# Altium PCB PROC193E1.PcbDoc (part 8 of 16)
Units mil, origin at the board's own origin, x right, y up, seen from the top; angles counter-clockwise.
Board outline 7700 x 2300 mil, 6 copper layers (Top Layer, GND 1, SIG 1, PWR, GND 2, Bottom Layer), stack 60.98 mil thick; 946 components, 667 nets, 9401 pads, 1730 vias.
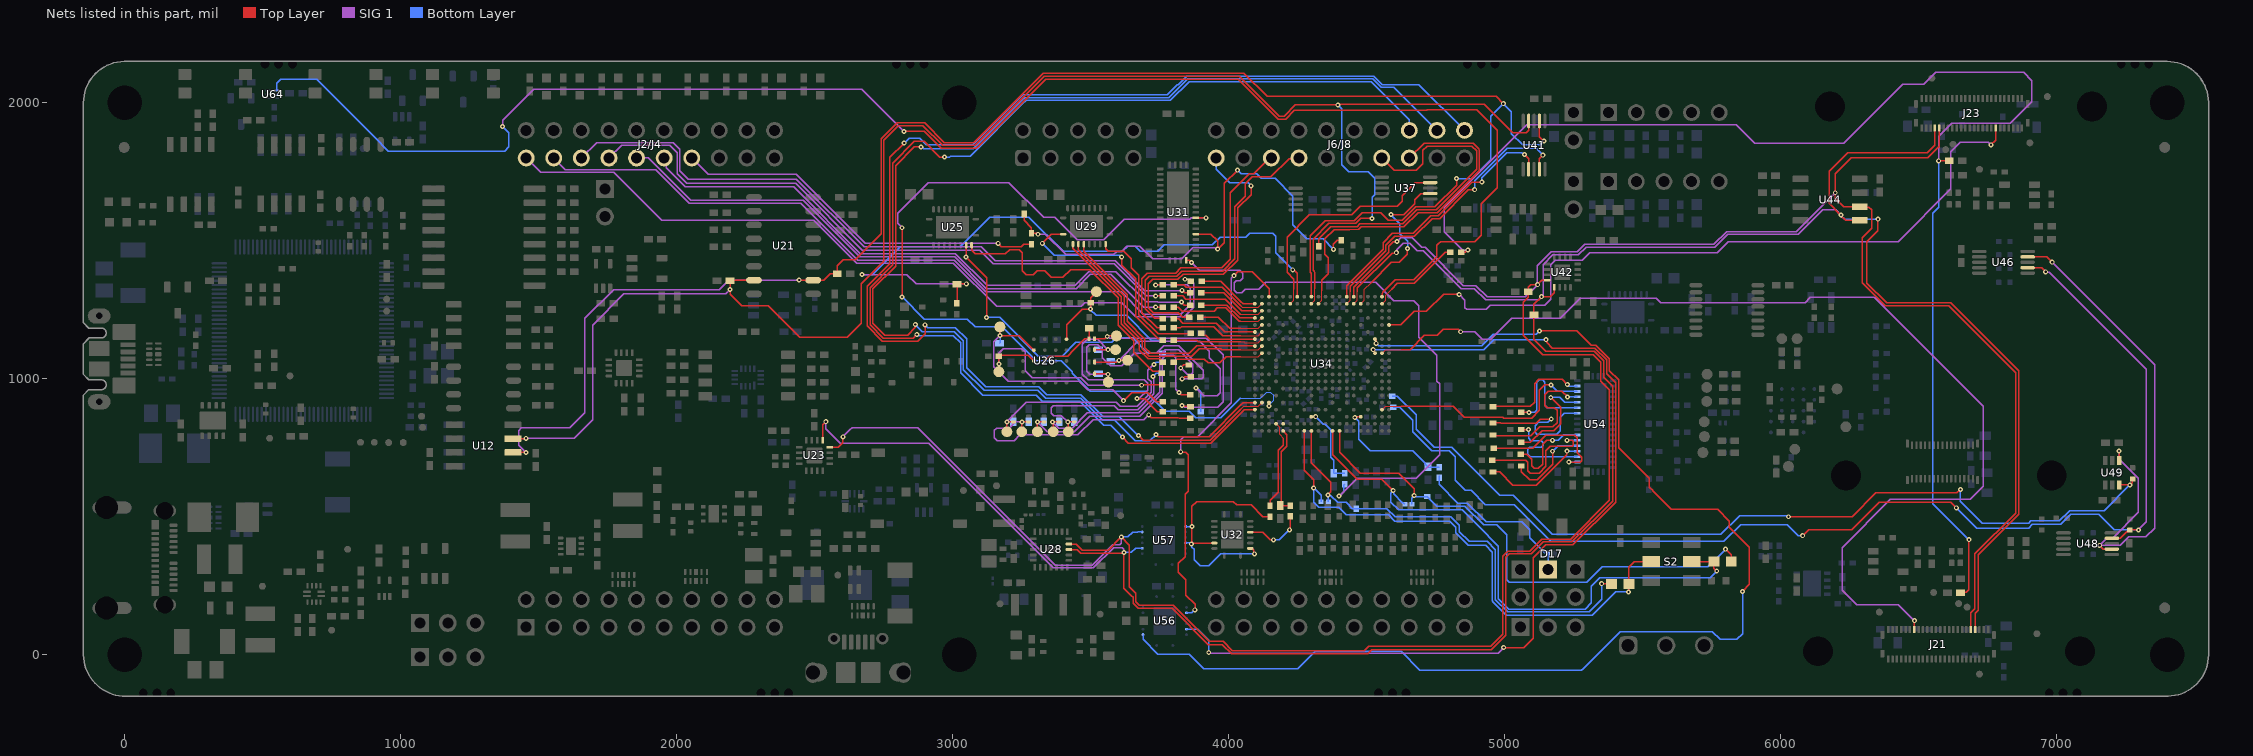
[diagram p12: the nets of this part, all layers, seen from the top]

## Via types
v1: diameter 18, hole 8, Top Layer to Bottom Layer, tented both sides, 1710 vias
v2: diameter 18, hole 8, Top Layer to Bottom Layer, tented top, 12 vias
v3: diameter 23.62, hole 11.81, Top Layer to Bottom Layer, tented both sides, 8 vias

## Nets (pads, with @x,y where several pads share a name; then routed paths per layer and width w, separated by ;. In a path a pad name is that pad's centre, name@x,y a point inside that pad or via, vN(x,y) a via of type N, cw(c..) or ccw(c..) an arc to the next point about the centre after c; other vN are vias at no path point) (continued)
AM261_ADC2_AIN5: R315.1 U31.21 | length 2081.7
  Top Layer w5.3: U31.21@3845.61,1429.75 3856.89,1429.75 v1(3865.32,1421.32)
  SIG 1 w4.75: v1(3865.32,1421.32) 3893.79,1392.84 4039.91,1392.84 4051,1381.76 4051,1365 4041.56,1355.56 4027.59,1355.56 4019.89,1347.85 4019.89,1320.44 4028.61,1311.72 4047.69,1311.72 4059.57,1323.6 4108.47,1323.6 4134.1,1349.23 4531.57,1349.23 4597.21,1283.59 4670.54,1283.59 4689.13,1265 4689.13,1150.02 4754.17,1084.98 4754.17,991.71 4764.6,981.28 4764.6,725.6 4678.9,639.9 4464.59,639.9 v1(4399.51,574.83)
  Bottom Layer w5.3: v1(4399.51,574.83) 4400.94,574.83 4416.39,590.27 4416.39,615.07 R315.1@4419.55,618.24
AM261_ADC2_AIN5_R: C195.2 R315.2 U34.V9 | length 291.8
  Top Layer w5.3: U34.V9@4299.21,862.57 4314.56,862.56 v1(4314.84,862.84)
  Bottom Layer w5.3: v1(4314.84,862.84) 4342.43,835.25 4350.06,835.25 4369.2,816.11 4369.2,767.84 4369.2,715.18 4379.69,704.7 C195.2@4379.69,658.31 4380.39,657.61 R315.2@4419.55,657.61
AM261_ADC2_AIN6: R136.1 U32.13 | length 218.4
  Top Layer w5.3: U32.13@4077.76,444.34 4123.6,444.34 4150.19,417.74 4161.25,417.74 v1(4162.41,416.58) ; v1(4219.9,452.91) 4219.9,456.34 4223.28,459.72 R136.1@4223.28,501.25
  Bottom Layer w5.3: v1(4162.41,416.58) 4183.58,416.58 v1(4219.9,452.91)
AM261_ADC2_AIN6_R: C90.2 R136.2 U34.Y5 | length 315.2
  Top Layer w5.3: C90.2@4186.24,540.73 4223.17,540.73 R136.2@4223.28,540.62 ; C90.2@4189.85,547.12 4189.85,735.85 4210.1,756.1 4210.1,798.13 U34.Y5@4196.85,811.38
AM261_ADC_CAL0: D17.1 J14.1 R307.1 | length 603.3
  Bottom Layer w5.3: R307.1@4762.73,649.07 4762.73,617.18 4830.22,549.68 4864.46,549.68 4932.96,481.18 5060.82,481.18 5089.67,452.33 5089.67,423.67 5143.89,369.44 5153.12,369.44 D17.1@5156.57,365.99 J14.1@5156.57,309.25
AM261_ADC_CAL0_R: C164.2 R307.2 U34.V16 | length 442.1
  Top Layer w5.3: v1(4456.52,860.06) 4459.02,862.57 U34.V16@4478.34,862.57
  Bottom Layer w5.3: v1(4456.52,860.06) 4471.02,845.56 4471.02,780.8 4511.7,740.12 4666.93,740.12 4712.57,694.48 4712.57,690.39 C164.2@4721.73,681.23 ; C164.2@4723.13,680.02 R307.2@4762.73,680.02
AM261_ADC_VREFHI_G0: C113.1 C166.1 S2.2 U34.Y12 | length 2138.3
  Top Layer w5.3: U34.Y12@4375.98,811.38 4375.98,725.09 4464.57,636.5 4553.95,636.5 v1(4595.63,594.82) ; S2.2@5676.66,337.83 5757.22,337.83 C113.1@5757.57,338.19 5757.57,313.53 v1(5767.94,303.16)
  Bottom Layer w5.3: C166.1@4637.72,545.95 4632.1,551.56 4628.84,551.56 4597.29,583.12 4597.29,593.16 v1(4595.63,594.82) 4595.63,593.45 4587.55,585.37 4587.55,552.42 4614.86,525.11 4845.97,525.11 4903,468.08 4977,394.09 4977,203.82 5014.88,165.93 5290.93,165.93 5313.32,188.32 5313.32,248.55 5344.22,279.45 5744.23,279.45 v1(5767.94,303.16)
AM261_ADC_VREFHI_G1: C111.1 C199.1 S2.5 U34.Y8 | length 1977.4
  Top Layer w5.3: U34.Y8@4273.62,811.38 4273.62,669.12 4308.05,634.69 4308.05,605.17 v1(4307.44,604.57) ; v1(5448.47,228.03) 5448.47,255.91 C111.1@5449.34,256.77 5449.34,317.67 5469.51,337.83 S2.5@5530.99,337.83
  Bottom Layer w5.3: C199.1@4334.68,554.56 4334.68,577.33 v1(4307.44,604.57) 4307.44,553.23 4325.2,535.48 4397.52,535.48 4425.88,507.12 4564.11,507.12 4564.41,506.82 4579.22,506.82 4601.92,484.13 4800.79,484.13 4822.14,462.78 4822.14,441.65 4867.72,396.06 4930.94,396.06 4955.4,371.6 4955.4,195.44 4956,194.84 4956,192.56 5005.75,142.8 5019.53,142.8 5019.73,143 5274.39,143 5274.59,142.8 5317.6,142.8 5402.82,228.03 v1(5448.47,228.03)
AM261_ADC_VREFLO_G0: C113.2 C166.2 R308.2 U34.Y13 | length 1918
  Top Layer w5.3: U34.Y13@4401.57,811.38 4401.57,733.27 4477.14,657.7 4615.46,657.7 4671.66,601.5 v1(4671.66,576.85) ; v1(5799.88,382.57) 5820.57,361.89 C113.2@5820.57,338.19
  Bottom Layer w5.3: C166.2@4663.7,545.95 4663.7,567.4 4671.66,575.36 v1(4671.66,576.85) 4674.25,576.85 4677.62,573.48 R308.2@4718.66,573.48 4753.62,538.53 4855.46,538.53 4923.63,470.36 4971.17,470.36 5006.69,434.85 5006.69,272.77 5016.78,262.68 5034.19,262.68 5034.37,262.86 5078.78,262.86 5078.96,262.68 5134.19,262.68 5134.37,262.86 5178.78,262.86 5178.96,262.68 5234.19,262.68 5234.37,262.86 5278.78,262.86 5278.96,262.68 5297.46,262.68 5352.94,318.15 5735.47,318.15 v1(5799.88,382.57)
AM261_ADC_VREFLO_G1: C111.2 C199.2 R314.2 U34.Y9 | length 1688.6
  Top Layer w5.3: U34.Y9@4299.21,811.38 4299.21,767.84 4299.21,695.3 4368.81,625.7 4368.81,589.87 4359.67,580.73 v1(4359.67,579.37) ; v1(5350.99,257.78) 5352.18,256.59 5386.16,256.59 C111.2@5386.35,256.77
  Bottom Layer w5.3: C199.2@4360.67,554.56 4360.67,578.37 v1(4359.67,579.37) 4362.1,576.94 4369.8,576.94 4394.49,552.24 4394.49,552.18 4424.86,552.18 4447.13,529.91 R314.2@4461.48,529.91 4573.07,529.91 4602.27,500.71 4803.97,500.71 4835.37,469.31 4835.37,445.73 4870.37,410.73 4936.27,410.73 4966,381 4966,199.83 5010.49,155.33 5295.32,155.33 5295.62,155.63 5305.92,155.63 5350.99,200.7 v1(5350.99,257.78)
AM261_ATESTV1: U34.W5
AM261_CLKOUT1: R157.1 R212.1 R213.1 | length 4873
  Top Layer w5.3: R157.1@4842.51,1457.97 4857.34,1457.97 v1@4865.9,1466.52 ; v1(6572.19,1789.93) 6572.34,1790.07 R213.1@6610.58,1790.07 ; R212.1@6651.32,224.48 6652.68,225.85 6671.91,225.85 6681.59,235.53 v1(6681.59,416.99)
  SIG 1 w4.75: v1(4865.97,1466.59) 4847.42,1466.59 4781.16,1532.85 4781.16,1621.74 5079.45,1920.03 5838.97,1920.03 5905.97,1853.03 6228.18,1853.03 6442.43,2067.28 6518.67,2067.28 6561.91,2110.52 6879.72,2110.52 6909.45,2080.79 6909.45,2002.93 6831.71,1925.19 6618.56,1925.19 6572.19,1878.83 v1(6572.19,1789.93)
  Bottom Layer w5.3: v1(6572.19,1789.93) 6572.19,1621.22 6550.49,1599.52 6550.49,548.09 v1(6681.59,416.99)
AM261_CLKOUT1_R: R157.2 U34.B19 | length 332.6
  Top Layer w3.94: U34.B19@4555.12,1272.01 4567.87,1284.77 4567.87,1292.27 4567.91,1292.3 4567.91,1302.9 4590.17,1325.16
  Top Layer w5.3: 4590.17,1325.16 4611.01,1346 4672.07,1346 4784.04,1457.97 R157.2@4800.14,1457.97
AM261_DAC_OUT: R134.1 U32.6 U32.10 U57.2 U57.5 | length 912.9
  Top Layer w5.3: v1(3864.16,401.48) 3867.6,401.48 3871.08,404.97 U32.6@3947.84,404.97 ; v1@3865.68,403 3865.68,464.02 v1(3866.46,464.8) 3866.46,537.98 3883.59,555.11 4016.71,555.11 4028.33,543.49 4080.99,543.49 4123.75,500.73 R134.1@4149.38,500.73 ; U32.10@4077.76,385.28 4083.73,385.28 4090.85,378.15 4090.85,368.31 v1(4093.28,365.88)
  Bottom Layer w5.3: U57.5@3843.79,405.78 3844.42,405.15 v1@3864.16,405.15 ; U57.2@3843.79,464.84 3844.67,463.95 3865.62,463.95 v1(3866.46,464.8) ; v1(3864.16,401.48) 3866.19,399.45 3866.19,390.14 3874.63,381.69 3874.63,344.66 3896.32,322.97 3927.34,322.97 3970.28,365.91 v1(4093.28,365.88)
AM261_DAC_OUT_R: R134.2 U34.W4 | length 328.2
  Top Layer w3.94: U34.W4@4171.26,836.97 4183.91,824.32 4183.91,816.82 4184.05,816.68 4184.05,799.09 4198.18,784.97
  Top Layer w5.3: R134.2@4149.38,540.1 4149.38,559.15 4179.25,589.02 4179.25,740.24 4179.44,740.43 4179.44,741.35 4198.18,760.09 4198.18,784.97
AM261_EPWM2_A: J2/J4.40 R132.1 | length 2829.5
  Top Layer w5.3: v1(3841.49,1360.7) 3855.19,1360.7 R132.1@3862.38,1353.51
  SIG 1 w4.75: J2/J4.40@1454.17,1800 1506.32,1747.85 1771.9,1747.85 1944.97,1574.79 2496.55,1574.79 2652.42,1418.92 3002.23,1418.92 3158.44,1262.71 3465.37,1262.71 3477.93,1275.27 3612.52,1275.27 3663.15,1224.64 3838.2,1224.64 3872.57,1259.01 3872.57,1346.24 3858.11,1360.7 v1(3841.49,1360.7)
AM261_EPWM2_A_R: R132.2 U34.B1 | length 226.5
  Top Layer w5.3: R132.2@3901.75,1353.51 3969.96,1353.51 4043.66,1279.82 4051.46,1272.01 4079.62,1272.01 U34.B1@4094.49,1272.01
AM261_EPWM2_B: J2/J4.39 R113.1 | length 2770
  Top Layer w5.3: v1(3734.96,1339.91) 3735.1,1340.06 R113.1@3760.72,1340.06
  SIG 1 w4.75: J2/J4.39@1554.17,1800 1596.27,1757.9 1924.41,1757.9 2045.54,1636.78 2449.38,1636.78 2655.79,1430.37 3004.92,1430.37 3120.14,1315.14 3609.57,1315.14 3690.02,1234.69 3826.41,1234.69 3860.12,1268.41 3860.12,1328.52 3848.59,1340.06 3735.1,1340.06 v1(3734.96,1339.91)
AM261_EPWM2_B_R: R113.2 U34.B2 | length 358.8
  Top Layer w3.94: 4043.66,1264.83 4049.27,1259.22 4107.28,1259.22 U34.B2@4120.08,1272.01
  Top Layer w5.3: R113.2@3800.09,1340.06 3837.2,1340.06 3845.11,1332.15 3976.34,1332.15 4043.66,1264.83
AM261_EPWM3_A: J2/J4.38 R124.1 | length 2500.5
  Top Layer w5.3: v1@3830.48,1320.4 v1(3830.35,1320.53) 3830.88,1320.53 3839.81,1311.59 R124.1@3860.17,1311.59
  SIG 1 w4.75: J2/J4.38@1654.17,1800 1709.56,1855.39 1986.95,1855.39 2010.77,1831.57 2010.77,1753.78 2041.27,1723.27 2432.79,1723.27 2678.29,1477.78 3103.82,1477.78 3153.85,1427.74 3587.88,1427.74 3695.82,1319.8 3829.63,1319.8 v1(3830.35,1320.53)
AM261_EPWM3_A_R: R124.2 U34.C1 | length 222.1
  Top Layer w5.3: R124.2@3899.54,1311.59 3982.33,1311.59 3998.35,1295.58 ; 3998.13,1295.36 4047.07,1246.42 U34.C1@4094.49,1246.42
AM261_EPWM3_B: J2/J4.37 R116.1 | length 2295.9
  Top Layer w5.3: v1(3735.1,1300.51) 3735.15,1300.55 R116.1@3760.84,1300.55
  SIG 1 w4.75: J2/J4.37@1754.17,1800 1799.81,1845.64 1974.67,1845.64 2001.02,1819.3 2001.02,1749.74 2001.1,1749.66 2001.1,1743.29 2036.59,1707.8 2430.24,1707.8 2672.07,1465.97 3097.35,1465.97 3146.22,1417.09 3584.31,1417.09 3700.85,1300.55 3700.9,1300.51 v1(3735.1,1300.51)
AM261_EPWM3_B_R: R116.2 U34.C2 | length 352.9
  Top Layer w3.94: 4043.66,1233.63 4107.28,1233.63 U34.C2@4120.08,1246.42
  Top Layer w5.3: R116.2@3800.21,1300.55 3832.56,1300.55 3844.32,1288.79 3986.25,1288.79 4041.41,1233.63 4043.66,1233.63
AM261_EPWM4_A: J2/J4.36 R112.1 | length 2173.9
  Top Layer w5.3: v1(3734.96,1260) 3735.83,1259.13 3760.52,1259.13 R112.1@3760.72,1258.93
  SIG 1 w4.75: J2/J4.36@1854.17,1800 1896.53,1800 2049.7,1646.83 2457.85,1646.83 2662.75,1441.92 3007.15,1441.92 3121.92,1327.16 3446.85,1327.16 3498.13,1378.43 3572.78,1378.43 3692.08,1259.13 3734.08,1259.13 v1(3734.96,1260)
AM261_EPWM4_A_R: R112.2 U34.D2 | length 356
  Top Layer w3.94: 4043.66,1208.04 4107.28,1208.04 U34.D2@4120.08,1220.83
  Top Layer w5.3: R112.2@3800.09,1258.93 3817.01,1258.93 3830.94,1245 3947.18,1245 3958.84,1256.66 3988.4,1256.66 4037.02,1208.04 4043.66,1208.04
AM261_EPWM4_B: J2/J4.35 R127.1 | length 2184.8
  Top Layer w5.3: v1(3828.23,1278.09) 3839.36,1266.96 R127.1@3860.48,1266.96
  SIG 1 w4.75: J2/J4.35@1954.17,1800 1961.1,1793.07 1961.1,1765.15 2031.26,1694.99 2423.9,1694.99 2665.47,1453.42 3009.44,1453.42 3124.26,1338.6 3443.16,1338.6 3493.04,1388.48 3590.38,1388.48 3700.48,1278.38 3742.57,1278.38 3742.86,1278.09 v1(3828.23,1278.09)
AM261_EPWM4_B_R: R127.2 U34.D1 | length 213.7
  Top Layer w5.3: R127.2@3899.85,1266.96 3993.09,1266.96 4039.22,1220.83 U34.D1@4094.49,1220.83
AM261_EPWM5_A: J6/J8.80 R123.1 | length 1093
  Top Layer w5.3: R123.1@3857.52,1223.03 3832.97,1223.03 3817.44,1238.56 3744.55,1238.56 3744.31,1238.81 3726.59,1238.81 3707.57,1257.83 3707.57,1344.2 3724.18,1360.81 3815.22,1360.81 3834.11,1379.7 3981.69,1379.7 3981.79,1379.8 3982.39,1379.8 4032.82,1430.24 4032.82,1619.42 4080.94,1667.53 v1(4080.94,1699.37)
  Bottom Layer w5.3: J6/J8.80@3954.17,1800 3954.17,1759.22 4002.69,1710.7 4069.61,1710.7 v1(4080.94,1699.37)
AM261_EPWM5_A_R: R123.2 U34.E2 | length 245.3
  Top Layer w3.94: 4043.66,1182.45 4107.28,1182.45 U34.E2@4120.08,1195.24
  Top Layer w5.3: R123.2@3896.89,1223.03 3962.22,1223.03 4002.81,1182.45 4043.66,1182.45
AM261_EPWM5_B: R131.1 U29.9 | length 556.9
  Top Layer w5.3: U29.9@3553.55,1488.24 3553.55,1470.35 3562.41,1461.49 3619.69,1461.49 3646.46,1434.71 3646.46,1402.54 3672.97,1376.03 3672.97,1232.91 3743.55,1162.33 3858.95,1162.33 R131.1@3861.35,1164.73
AM261_EPWM5_B_R: R131.2 U34.G1 | length 202.3
  Top Layer w5.3: R131.2@3900.72,1164.73 3906.88,1158.57 3917.2,1158.57 3931.71,1144.06 4043.66,1144.06 U34.G1@4094.49,1144.06
AM261_EPWM6_A: J6/J8.78 R117.1 | length 1013.9
  Top Layer w5.3: R117.1@3760.23,1180.67 R117.1@3760.72,1180.17 ; R117.1@3760.86,1184.33 3740.4,1184.33 3684.72,1240.02 3684.72,1362 3704.98,1382.26 3807.54,1382.26 3826.77,1401.49 3973.92,1401.49 4005.24,1432.81 4005.24,1673.72 4074.04,1742.52 4090.62,1742.52 4148.11,1800 J6/J8.78@4154.17,1800
AM261_EPWM6_A_R: R117.2 U34.F2 | length 343.8
  Top Layer w3.94: 4043.66,1156.86 4107.28,1156.86 U34.F2@4120.08,1169.65
  Top Layer w5.3: R117.2@3800.09,1180.17 R117.2@3802.24,1182.32 ; R117.2@3800.24,1184.33 3823.87,1184.33 3829,1189.46 3945.94,1189.46 3978.55,1156.86 4043.66,1156.86
AM261_EPWM6_B: J6/J8.77 R118.1 | length 1059.5
  Top Layer w5.3: R118.1@3761.02,1218.92 3731.92,1218.92 3696.46,1254.38 3696.46,1356.42 3711.7,1371.66 3811.5,1371.66 3829.84,1390 3977.42,1390 4022.22,1434.8 4022.22,1619.46 4022.22,1623.81 4060.41,1662 4060.41,1706.46 4085.39,1731.43 4152.76,1731.43 4218.81,1797.49 4251.66,1797.49 J6/J8.77@4254.17,1800
AM261_EPWM6_B_R: R118.2 U34.F1 | length 313.7
  Top Layer w5.3: R118.2@3800.47,1217.23 3817.77,1217.23 3833.62,1201.38 3953.67,1201.38 3985.41,1169.65 U34.F1@4094.49,1169.65
AM261_EPWM7_A: R111.1 U29.1 | length 767.7
  Top Layer w5.3: v1(3324.24,1490.98) 3356.93,1523.67 U29.1@3400.01,1523.67 ; v1(3611.92,1441.47) 3611.92,1412.08 3662.36,1361.64 3662.36,1226.18 3744.07,1144.47 3756.37,1144.47 R111.1@3760.72,1140.12
  Bottom Layer w5.3: v1(3324.24,1490.98) 3367.74,1447.48 3602.47,1447.48 3608.48,1441.47 v1(3611.92,1441.47)
AM261_EPWM7_A_R: R111.2 U34.G2 | length 329
  Top Layer w3.94: 4043.66,1133.76 4055.24,1133.76 4057.73,1131.27 4099.79,1131.27 4107.28,1131.27 U34.G2@4120.08,1144.06
  Top Layer w5.3: R111.2@3800.09,1140.12 3801.18,1139.04 3883.37,1139.04 3888.65,1133.76 4043.66,1133.76
AM261_EPWM7_B: R115.1 U29.3 | length 587
  Top Layer w5.3: U29.3@3435.44,1488.24 3435.44,1472.23 3610.86,1296.81 3610.86,1199.1 3675.76,1134.2 3675.76,1104.02 3708,1071.78 3749.16,1071.78 R115.1@3760.84,1060.1
AM261_EPWM7_B_R: R115.2 U34.J2 | length 345.6
  Top Layer w3.94: 4043.66,1080.09 4107.28,1080.09 U34.J2@4120.08,1092.88
  Top Layer w5.3: R115.2@3800.21,1060.1 3802.18,1060.1 3809.37,1067.29 3809.37,1068.35 3812.48,1071.46 3893.24,1071.46 3893.36,1071.34 3911.72,1071.34 3925.57,1057.49 3968.02,1057.49 3990.61,1080.09 4043.66,1080.09
AM261_GPIO1: J6/J8.51 U34.T2 | length 4737.4
  Top Layer w3.94: 4043.66,889.63 4054.98,900.95 4107.28,900.95 U34.T2@4120.08,913.75
  Top Layer w5.3: v1(2823.83,1854.29) 2771.72,1802.18 2771.72,1511.94 2771.72,1417.24 2689.46,1334.99 2689.46,1191.58 2744.13,1136.91 2873.41,1136.91 2899.31,1162.82 v1(2899.31,1195.75) ; v1(3673.18,794.74) 3689.87,778.05 3932.07,778.05 4043.66,889.63
  Bottom Layer w5.3: v1(2823.83,1854.29) 2841.56,1872.02 2879.43,1872.02 2903.35,1848.09 3072.69,1848.09 3254.27,2029.68 3776.42,2029.68 3812.79,2066.06 3816.3,2066.06 3847.29,2097.05 4525.09,2097.05 4556.09,2066.06 4688.11,2066.06 J6/J8.51@4854.17,1900 ; v1(2899.31,1195.75) 2909.83,1185.23 3009.55,1185.23 3050.53,1144.25 3050.53,1040.82 3119.6,971.75 3312.2,971.75 3341.23,942.73 3464.43,942.73 3545.42,861.73 3603.81,861.73 3670.8,794.74 v1(3673.18,794.74)
AM261_GPIO5: J6/J8.52 U34.T1 | length 4503.7
  Top Layer w5.3: v1(2864.13,1196.48) 2864.13,1186.22 2836.02,1158.11 2752.92,1158.11 2710.66,1200.36 2710.66,1326.21 2792.91,1408.46 2792.91,1502.95 2792.91,1772.04 2860.93,1840.05 v1(2885.02,1840.05) ; v1(3736.59,798.14) 3744.41,790.32 3840.3,790.32 3840.41,790.43 3882.18,790.43 3928.83,790.43 4043.66,905.26 4052.14,913.75 U34.T1@4094.49,913.75
  Bottom Layer w5.3: v1(2864.13,1196.48) 2889.58,1171.03 3006.1,1171.03 3038.66,1138.46 3038.66,1032.83 3113.51,957.97 3307.06,957.97 3336.04,928.99 3463.6,928.99 3542.73,849.86 3586.97,849.86 3661.62,775.21 3714.14,775.21 3736.59,797.66 v1(3736.59,798.14) ; v1(2885.02,1840.05) 2888.16,1840.05 2894.48,1833.74 3074.66,1833.74 3255.26,2014.34 3256.36,2014.34 3261.1,2019.08 3783.28,2019.08 3819.96,2055.76 3820.56,2055.76 3851.55,2086.75 4520.83,2086.75 4551.82,2055.76 4598.41,2055.76 J6/J8.52@4754.17,1900
AM261_GPIO6: J6/J8.53 U34.U1 | length 4452.8
  Top Layer w5.3: v1(2869.72,1160.83) 2856.4,1147.51 2748.52,1147.51 2700.06,1195.97 2700.06,1330.6 2782.32,1412.85 2782.32,1507.55 2782.32,1781.08 2861.19,1859.95 2895.68,1859.95 2952.19,1803.44 v1(2969.84,1803.44) ; v1(3615.04,788.66) 3636.58,767.11 3935.47,767.11 3936.12,767.75 3936.34,767.75 4056.75,888.16 U34.U1@4094.49,888.16
  Bottom Layer w5.3: v1(2869.72,1160.83) 2874.28,1156.27 3002.07,1156.27 3028.06,1130.28 3028.06,1021.91 3109.29,940.67 3302.31,940.67 3324.31,918.66 3459.36,918.66 3546.24,831.78 3571.91,831.78 v1(3615.04,788.66) ; v1(2969.84,1803.44) 2988.11,1803.44 2991.59,1806.92 3062.41,1806.92 3259.52,2004.04 3261.47,2004.04 3265.8,2008.37 3787.74,2008.37 3855.82,2076.45 4516.56,2076.45 4654.17,1938.84 J6/J8.53@4654.17,1900
AM261_GPIO46: U34.A3 U56.3 | length 1601.2
  Top Layer w5.3: v1(3825.76,735.54) 3828.09,733.22 3843.51,733.22 3852.41,724.31 3852.41,593.06 3841.73,582.37 3841.73,356.08 3817.45,331.8 3817.45,299.16 3844.71,271.9 3844.71,215.95 3877.81,182.85 3877.81,163.95 v1(3876.92,163.05) ; v1(4019.21,1373.59) 4032.86,1387.25 4084.72,1387.25 4145.67,1326.3 U34.A3@4145.67,1297.6
  SIG 1 w4.75: v1(3825.76,735.54) 3825.51,735.8 3825.51,779.27 3836.56,790.32 3886.94,790.32 4009.11,912.49 4009.11,1363.5 v1(4019.21,1373.59)
  Bottom Layer w5.3: U56.3@3846.65,151.94 3865.81,151.94 v1(3876.92,163.05)
AM261_GPIO90: U34.J18 U56.6 | length 3453.6
  Top Layer w5.3: v1(4523.28,1105.32) U34.J18@4529.52,1092.88 ; v1(4996,26) 5069.34,26 5102.42,59.07 5102.42,352.33 5148.93,398.84 5246.96,398.84 5401.57,553.46 5401.57,985.68 5368.57,1018.69 5368.57,1068.79 5326.07,1111.28 5309.4,1111.28 5309.15,1111.53 5172.77,1111.53 5151.63,1132.68 5151.63,1139.25 v1(5149.2,1141.68)
  SIG 1 w4.75: v1(3927.32,8.24) 3929.69,5.86 4975.86,5.86 4984.77,14.77 v1(4996,26)
  Bottom Layer w5.3: U56.6@3846.65,92.88 3887.61,92.88 3927.74,52.75 3927.74,8.66 v1(3927.32,8.24) ; v1(4523.28,1105.32) 4923.52,1105.32 4959.89,1141.68 v1(5149.2,1141.68)
AM261_GPIO106: U34.G18 U56.10 | length 4611.9
  Top Layer w5.3: U34.G18@4529.52,1144.06 4533.99,1139.6 v1@4533.99,1129.08 ; v1(5126.1,1173.28) 5127.28,1174.46 5260.78,1174.46 5302.23,1133.02 5313.67,1121.58 5330.34,1121.58 5379.17,1072.76 5379.17,1029.91 5412.68,996.39 5412.68,750.68 5523.07,640.29 5523.07,607.63 5535.42,595.29 5535.42,595.01 5546.86,583.57 5547.13,583.57 5603.41,527.29 5770.84,527.29 5813.57,484.55 5813.57,463.02 5886.48,390.11 5886.48,254.71 v1(5861.43,229.66)
  Bottom Layer w5.3: U56.10@3689.17,73.2 3689.17,55.69 3742.85,2.01 3856.82,2.01 3909.84,-51 4250,-51 4313,12 4624,12 4692.15,-56.15 5276.85,-56.15 5279.65,-53.35 5280.27,-53.35 5417.79,84.17 5751.29,84.17 5780.02,55.44 5839.84,55.44 5861.43,77.03 v1(5861.43,229.66) ; v1(4533.99,1128.58) 4542.46,1120.12 4917.01,1120.12 4958.35,1161.46 5114.28,1161.46 v1(5126.1,1173.28)
AM261_GPIO136: U34.B14 U41.4 | length 1072.4
  Top Layer w3.94: U34.B14@4427.16,1272.01 4440.05,1284.9 4440.05,1292.22 4439.96,1292.3 4439.96,1315.32
  Top Layer w5.3: 4439.96,1315.32 4439.96,1334.76 4569.43,1464.23 4569.43,1484.57 4579.41,1494.55 4589.95,1505.09 4589.95,1505.26 4601.39,1516.7 4601.56,1516.7 4601.75,1516.89 4671.94,1516.89 4672.24,1517.19 4672.67,1517.19 4736.25,1580.77 4763.96,1580.77 4868.36,1685.18 v1(4891.02,1685.18) ; U41.4@5125.61,1759.01 5125.61,1798.06 v1(5137.84,1810.29)
  Bottom Layer w5.3: v1(4891.02,1685.18) 4891.02,1717.5 5009.07,1835.54 5114.71,1835.54 5137.84,1812.41 v1(5137.84,1810.29)
AM261_GPIO137: U34.A14 U41.2 | length 969.4
  Top Layer w5.3: U34.A14@4427.16,1297.6 4427.16,1336.62 4438.97,1348.43 4523.27,1432.73 4538.6,1448.06 4543.27,1452.73 4543.27,1452.98 4558.83,1468.53 4558.83,1493.37 4592.64,1527.19 4667.68,1527.19 4731.87,1591.39 4759.58,1591.39 4880.76,1712.57 v1(4916.64,1712.57) ; v1(5071,1813) 5086.24,1797.76 U41.2@5086.24,1759.01
  Bottom Layer w5.3: v1(4916.64,1712.57) 4916.64,1728.12 5007.71,1819.19 5061.55,1819.19 5067.74,1813 v1(5071,1813)
AM261_I2C0_SCL: J21.40 J23.40 R183.1 U23.12 U28.23 U34.A15 U42.12 U44.6 U57.14 | length 10037.7
  Top Layer w5.3: U23.12@2553.81,751.68 2585.85,751.68 2602.17,768 v1(2602.17,789.9) ; U28.23@3420.91,401.23 3421.06,401.07 3447.6,401.07 3469.72,378.95 3562.41,378.95 v1(3610.68,427.23) 3640.11,397.8 3640.11,246.18 3663.71,222.58 3663.71,191.33 3676.32,178.72 3798.5,178.72 3928.85,48.37 3979.08,48.37 4013.1,14.35 4490.27,14.35 4490.34,14.42 4491.18,14.42 4507.83,31.07 4948.74,31.07 4987.31,69.64 4992.37,74.69 4992.37,75.54 4992.6,75.77 4992.6,357.15 5011.2,375.76 5090.87,375.76 5134.55,419.44 5238.43,419.44 5379.17,560.18 5379.17,960.04 5347.37,991.84 5347.37,1060.55 5320.02,1087.9 5136.74,1087.9 5067,1157.64 5067,1278 5084.86,1295.86 R183.1@5084.86,1315.92 5084.86,1332.53 5093.25,1340.92 v1(5119.23,1340.92) 5118.47,1341.69 5118.47,1341.95 5133.2,1356.69 U42.12@5153.4,1356.69 ; U34.A15@4452.75,1297.6 4452.75,1331.97 4579.73,1458.95 4579.73,1479.93 4596.54,1496.74 4609.04,1496.74 v1(4609.47,1497.17) ; J23.40@6574.2,1908.44 6574.2,1843.23 6531.76,1800.79 6254.77,1800.79 6197.24,1743.26 v1(6197.24,1674.12) 6197.24,1654.73 6227.92,1624.05 U44.6@6285.74,1624.05 6287.56,1622.22 6319.13,1622.22 6329.73,1611.62 6329.73,1546.18 6294.98,1511.43 6294.98,1348.35 6379.2,1264.13 6608.01,1264.13 6851.01,1021.13 6851.01,513.72 6703.14,365.85 6703.14,205.39 6703.14,167.35 6688.27,152.48 J21.40@6688.27,91.39
  SIG 1 w4.75: v1(2602.17,789.9) 2627.35,815.08 2634.88,822.61 2872.93,822.61 3370.38,325.15 3505.88,325.15 3579.86,399.13 3605.17,399.13 3610.68,404.64 v1(3610.68,427.23) ; v1(4609.47,1497.17) 4622.77,1510.47 4664.46,1510.47 4698.88,1476.05 4710.87,1476.05 4849.24,1337.69 4895.31,1337.69 4936.36,1296.64 5074.94,1296.64 v1(5119.23,1340.92) 5118.47,1341.69 5118.47,1409.85 5168.61,1460 5263.11,1460 5290.12,1487.01 5757.72,1487.01 5804.07,1533.35 6056.48,1533.35 v1(6197.24,1674.12)
  Bottom Layer w5.3: v1(3610.68,427.23) 3633.85,427.23 3651.52,444.89 3670.14,444.89 3670.4,445.15 U57.14@3686.31,445.15
AM261_I2C0_SDA: J21.42 J23.42 R185.1 U23.13 U28.22 U34.B15 U42.13 U44.5 U57.11 | length 10148.3
  Top Layer w3.94: U34.B15@4452.75,1272.01 4465.55,1284.81 4465.55,1302.9 4465.55,1315.32
  Top Layer w5.3: U23.13@2528.22,777.27 2528.22,832.82 v1(2539.92,844.52) ; U28.22@3420.91,381.54 3421.05,381.4 3451.63,381.4 3464.38,368.65 3617.64,368.65 v1(3619.93,370.94) 3619.93,241.86 3647.24,214.55 3653.07,208.72 3653.07,187.05 3671.98,168.14 3794.51,168.14 3926.22,36.43 3976.45,36.43 4009.93,2.96 4502.96,2.96 4518.58,18.58 4951.25,18.58 5002.97,70.3 5002.97,352.75 5015.68,365.46 5095.13,365.46 5138.81,409.14 5242.69,409.14 5390.38,556.83 5390.38,972.32 5357.97,1004.74 5357.97,1064.82 5323.19,1099.59 5148.66,1099.59 5105.04,1143.22 5105.04,1231.37 R185.1@5105.5,1231.83 5105.5,1269.72 v1(5133.2,1297.43) 5164.49,1297.43 5178.99,1311.93 U42.13@5178.99,1331.1 ; 4465.55,1315.32 4465.55,1328.98 4591.75,1455.18 4605,1455.18 v1(4606.77,1456.95) ; U44.5@6285.74,1574.05 6235.01,1574.05 6218,1591.06 v1(6218,1593) 6175.56,1635.44 6175.56,1751.23 6243.15,1818.82 6530.65,1818.82 6558.45,1846.62 J23.42@6558.45,1908.44 ; v1(6351.66,1578.24) 6351.66,1536.5 6312.27,1497.12 6312.27,1345.62 6383.16,1274.73 6616.63,1274.73 6861.31,1030.05 6861.31,509.03 6714.82,362.54 6714.82,205.39 6714.82,161.96 6704.02,151.16 J21.42@6704.02,91.39
  SIG 1 w4.75: v1(2539.92,844.52) 2539.92,819.19 2592.52,766.58 2912.92,766.58 3364.83,314.67 3509.19,314.67 3582.91,388.39 3614.75,388.39 3619.93,383.21 v1(3619.93,370.94) ; v1(4606.77,1456.95) 4608.77,1458.95 4608.77,1468.25 4631.45,1490.93 4655.82,1490.93 4682.37,1464.38 4704.71,1464.38 4842.49,1326.59 4889.36,1326.59 4931.28,1286.89 5122.66,1286.89 v1(5133.2,1297.43) 5138.48,1302.7 5138.48,1413.68 5173.84,1449.04 5266.71,1449.04 5294.58,1476.9 5761.41,1476.9 5808.11,1523.6 6063.69,1523.6 6152.63,1612.54 6198.46,1612.54 v1(6218,1593)
  Bottom Layer w5.3: v1(3619.93,370.94) 3647.1,370.94 3662.26,386.1 U57.11@3686.31,386.1 ; v1(6218,1593) 6218,1591.06 6230.82,1578.24 v1(6351.66,1578.24)
AM261_I2C1_SCL: R57.1 U12.3 U21.15 U34.B9 U41.9 | length 6253.7
  Top Layer w3.94: U34.B9@4299.21,1272.01 4312,1284.81 4312,1326.07
  Top Layer w5.3: U12.3@1406.3,783.03 1452.6,783.03 v1(1454.1,784.53) ; U21.15@2279.55,1357.42 2194.6,1357.42 R57.1@2192.97,1355.79 v1(2192.97,1323.1) 2193.65,1322.41 2193.65,1306.15 2234.78,1265.02 2330.54,1265.02 2444.6,1150.95 2618.35,1150.95 2640.87,1173.47 2668.26,1200.87 2668.26,1343.77 2750.51,1426.02 2750.51,1520.72 2750.51,1864.75 2803.19,1917.42 2891.71,1917.42 2963.44,1845.69 2996.82,1845.69 3080.84,1845.69 3331.9,2096.75 4038.05,2096.75 4183.09,1951.7 4200.49,1951.7 4206.23,1957.43 4238.04,1989.25 4241.14,1992.36 v1(4394.89,1992.36) 4396.9,1994.37 4925.98,1994.37 5028.46,1891.9 5076.83,1891.9 5086.24,1901.31 U41.9@5086.24,1934.2 ; 4312,1326.07 4312,1386.3 4308.83,1389.48 4305.74,1392.57 4305.74,1424.44 4305.53,1424.64 4305.53,1496.35 4305.68,1496.5 4305.68,1506.18 4362.21,1562.7 4458.66,1562.7 4458.88,1562.92 4460.76,1562.92 4478.97,1581.14 v1(4519.1,1581.14)
  SIG 1 w4.75: v1(1454.1,784.53) 1628.83,784.53 1695.21,850.9 1695.21,1194.45 1808.18,1307.42 2177.29,1307.42 v1(2192.97,1323.1)
  Bottom Layer w5.3: v1(4394.89,1992.36) 4408.87,1978.38 4408.87,1774.69 4433.74,1749.82 4505.18,1749.82 4528.69,1726.3 4528.69,1666.76 4519.1,1657.17 v1(4519.1,1581.14)
AM261_I2C1_SDA: R73.1 U12.2 U21.2 U34.A9 U41.7 | length 6391.7
  Top Layer w5.3: U12.2@1406.3,733.03 v1(1453.12,733.03) ; v1(2443.56,1357.47) 2494.12,1357.47 2532.78,1357.47 ; U21.2@2494.12,1357.42 2532.73,1357.42 2556.67,1381.36 R73.1@2580.82,1381.36 2580.82,1408.84 2603.2,1431.22 2646.02,1431.22 2739.91,1525.11 2739.91,1869.14 2798.8,1928.02 2897.86,1928.02 2969.9,1855.99 3001.16,1855.99 3076.58,1855.99 3327.94,2107.35 4054,2107.35 4138.44,2022.91 4968.26,2022.91 v1(4994.46,1996.71) ; U34.A9@4299.21,1297.6 4299.21,1383.02 4295.56,1386.68 4295.57,1388.17 4295.44,1388.3 4295.44,1420.17 4295.23,1420.38 4295.23,1500.62 4295.38,1518.53 4349.85,1573 4454.39,1573 4483.2,1601.81 4550.49,1601.81 4572.23,1580.07 4572.23,1579.96 4577.41,1574.78 4629.33,1574.78 4677.74,1623.19 4746.41,1623.19 4825.12,1701.9 v1(4825.12,1725.4) ; U41.7@5125.61,1934.2 5125.61,1877.72 v1(5141.97,1861.36)
  SIG 1 w4.75: v1(1453.12,733.03) 1426.56,759.59 1426.56,812.41 1436.31,822.16 1612.92,822.16 1667.18,876.42 1667.18,1218.52 1771.76,1323.1 2154.17,1323.1 2188.55,1357.47 v1(2443.56,1357.47)
  Bottom Layer w5.3: v1@4825.12,1725.53 4880.85,1725.53 4949.27,1793.95 4949.27,1951.52 v1(4994.46,1996.71) 5024.14,1967.03 5024.14,1888.76 5064.53,1848.36 5128.98,1848.36 v1(5141.97,1861.36)
AM261_INT_PB_GPIO124: U34.A19 U64.4 | length 5929.4
  Top Layer w5.3: v1(2822.93,1896.22) 2896.51,1896.22 2957.34,1835.39 2992.07,1835.39 3085.11,1835.39 3094.97,1845.25 3335.87,2086.15 4033.65,2086.15 4151.9,1967.9 4178.7,1941.1 4205.81,1941.1 4237.55,1972.84 4717.07,1972.84 4719.91,1975.67 4898.08,1975.67 4900.92,1972.84 4972.98,1900.77 4972.98,1691.45 4915.09,1633.55 4915.09,1520.52 4890.97,1496.39 4767.24,1496.39 4759.28,1488.43 4753.96,1483.12 4753.96,1478.44 4753.96,1448.59 4753.96,1442.88 4670.51,1359.43 4603.8,1359.43 4580.35,1335.98 4557.92,1313.55 4555.12,1310.74 U34.A19@4555.12,1297.6
  SIG 1 w4.75: v1(1369,1914) 1369,1936.28 1481.77,2049.05 2670.1,2049.05 v1(2822.93,1896.22)
  Bottom Layer w5.3: U64.4@551.18,2043.98 551.18,2070.96 565.91,2085.69 694.59,2085.69 903.65,1876.63 903.65,1876.56 954.94,1825.27 1376.27,1825.27 1391.94,1840.94 1391.94,1891.06 v1(1369,1914)
AM261_LED_GPIO84: R85.2 R86.1 U34.A7 | length 2430
  Top Layer w5.3: R86.1@3014.94,1273.82 3015.51,1274.38 R85.2@3015.51,1342.04 3017.73,1344.26 v1(3048.88,1344.26) ; v1(4231.65,1394.98) 4234.65,1394.98 4248.03,1381.6 U34.A7@4248.03,1297.6
  SIG 1 w4.75: v1(2671.37,1377.88) 2833.2,1377.88 2866.82,1344.26 v1(3048.88,1344.26)
  Bottom Layer w5.3: v1(2671.37,1377.88) 2707.71,1377.88 2808.82,1478.99 3027.67,1478.99 3134.35,1585.67 3275.33,1585.67 3399.59,1461.41 3614.46,1461.41 3633.07,1480.02 3660.78,1480.02 3678.58,1462.22 3743.24,1462.22 3766.17,1485.15 3824.52,1485.15 3824.8,1484.87 3939.9,1484.87 3968.23,1513.19 4061.95,1513.19 4076.26,1527.49 4158.61,1527.49 4169.85,1516.25 4169.85,1456.77 v1(4231.65,1394.98)
AM261_LIN1_RXD: U31.29 U34.T3 | length 3260.4
  Top Layer w5.3: v1(2816.02,1547.3) 2816.02,1296.89 v1(2816.1,1296.81) ; U31.29@3881.04,1583.29 v1(3917.06,1583.29) ; U34.T3@4145.67,913.75 U34.T3@4145.67,913.75 v1(4145.75,901.55) v1(4145.75,901.55)
  SIG 1 w4.75: v1(2816.02,1547.3) 2800.21,1563.12 2800.21,1599.21 2911.81,1710.81 3203.19,1710.81 3328.65,1585.35 3368.65,1585.35 3450.53,1503.47 3546.9,1503.47 3621.97,1578.55 3858.3,1578.55 3863.05,1583.29 v1(3917.06,1583.29)
  Bottom Layer w3.94: 4043.66,929.05 4114,929.05 4137.07,952.12 4150.79,952.12 4162.9,940.01 4162.9,922.23 4145.75,905.08 v1(4145.75,901.55)
  Bottom Layer w5.3: v1(2816.1,1296.81) 2896.42,1216.49 3053.19,1216.49 3081.63,1188.05 3179.44,1188.05 3301.74,1065.75 3392.61,1065.75 3433.67,1024.69 3433.67,1019.33 3497.69,955.31 3696.93,955.31 3770.13,882.11 3856.56,882.11 3880.54,858.13 3971.02,858.13 4041.94,929.05 4043.66,929.05
AM261_LIN1_TXD: J2/J4.34 R96.2 | length 1367.3
  Top Layer w5.3: v1(3164.52,1490.8) 3176,1479.32 3247.47,1479.32 3256.21,1488.06 R96.2@3285.03,1488.06
  SIG 1 w4.75: J2/J4.34@2054.17,1800 2113.36,1740.81 2433,1740.81 2683.01,1490.8 v1(3164.52,1490.8)
AM261_LIN1_TXD/PR1_PRU1_GPIO8/OSPI1_RST: R93.1 R96.1 R144.1 U31.26 | length 1846.9
  Top Layer w5.3: R93.1@3258.14,1597.13 3258.14,1574.76 3285.03,1547.87 R96.1@3285.03,1527.43 v1@3306.1,1527.43 ; U31.26@3881.04,1524.24 3908.86,1524.24 3908.97,1524.35 3934.97,1524.35 3959.88,1499.44 v1(3959.88,1470.35) 3960.97,1470.35 3983.73,1493.11 3983.73,1707.66 v1(4031.75,1755.68) ; v1(4379.19,1469.07) 4379.19,1487.74 4393.21,1501.76 4407.65,1501.76 R144.1@4407.89,1502
  SIG 1 w4.75: v1(3309.2,1523.69) 3335.78,1523.69 3409.06,1450.42 3583.42,1450.42 3593.72,1460.72 3611.81,1460.72 3630.84,1479.75 3678.2,1479.75 3723.85,1434.1 3828.79,1434.1 3868.76,1474.06 3956.17,1474.06 v1(3959.88,1470.35)
  Bottom Layer w5.3: 4282.83,1506.82 4341.44,1506.82 v1(4379.19,1469.07)
  Bottom Layer w5.32: v1(4031.75,1755.68) 4044.92,1742.51 4101.37,1742.51 4117.95,1725.92 4168.43,1725.92 4232.26,1662.09 4232.26,1557.38 4282.83,1506.82
AM261_LIN2_RXD: J6/J8.73 U34.B10 | length 1278.7
  Top Layer w3.94: U34.B10@4324.8,1272.01 4337.6,1284.81 4337.6,1318.68
  Top Layer w5.3: 4337.6,1318.68 4337.6,1356.83 4360.69,1379.92 4360.69,1439.42 4348.41,1451.7 4348.41,1507.62 4381.53,1540.74 4438.31,1540.74 4470.39,1541.39 4479.56,1550.56 4634.26,1550.56 4685.68,1601.99 4755.19,1601.99 4906.67,1753.46 4906.67,1753.88 4908.03,1755.24 4908.03,1830.58 4905.51,1833.1 4884.97,1853.63 4873.14,1853.63 4707.81,1853.63 J6/J8.73@4654.17,1800
AM261_LIN2_TXD: J6/J8.74 R141.1 | length 1204.1
  Top Layer w5.3: R141.1@4325.9,1480.18 4325.9,1507.43 4370.23,1551.76 4464.65,1551.76 4474.05,1561.16 4630.29,1561.16 4681.42,1612.29 4681.83,1612.29 4682.13,1612.59 4682.86,1612.59 4693.22,1612.59 4709.79,1612.59 4750.8,1612.59 4897.73,1759.51 4897.73,1826.31 4880.71,1843.33 4718.6,1843.33 4702.53,1827.27 4702.53,1778.95 4678.96,1755.37 4598.8,1755.37 J6/J8.74@4554.17,1800
AM261_MCAN0_RX: U29.4 U34.H2 | length 937.5
  Top Layer w3.94: 4043.66,1105.68 4107.28,1105.68 U34.H2@4120.08,1118.47
  Top Layer w5.3: U29.4@3455.13,1488.24 3455.13,1467.11 3614.72,1307.52 3621.16,1301.07 3621.16,1203.37 3686.06,1138.47 3686.06,1108.71 3712.39,1082.38 3807.5,1082.38 3865.86,1082.38 3892.12,1108.64 3971,1108.64 3973.96,1105.68 4043.66,1105.68
AM261_MCAN0_TX: U29.5 U34.H1 | length 885.1
  Top Layer w5.3: U29.5@3474.81,1488.24 3474.81,1461.99 3625.02,1311.78 3631.46,1305.34 3631.46,1207.64 3696.36,1142.74 3696.36,1113.4 3716.78,1092.98 3803.11,1092.98 3856.46,1092.98 3881.95,1118.47 3883.6,1120.12 3913.56,1120.12 4079.62,1120.12 4092.84,1120.12 U34.H1@4094.49,1118.47
AM261_MCAN1_RX: U34.B6 U37.9 | length 868.9
  Top Layer w3.94: U34.B6@4222.44,1272.01 4235.23,1284.81 4235.23,1325.16
  Top Layer w5.3: 4235.23,1325.16 4235.23,1361.16 4211.08,1385.31 4211.08,1513.71 4291.37,1594 4445,1594 4476.16,1625.16 4488.55,1625.16 4488.74,1624.96 4600.14,1624.96 4600.33,1625.16 4609.47,1625.16 4627.85,1643.53 4627.85,1663.32 4675.5,1710.97 4700.12,1710.97 4700.32,1710.77 U37.9@4729.47,1710.77
AM261_MCAN1_TX: U34.B16 U37.7 | length 617.1
  Top Layer w3.94: U34.B16@4478.34,1272.01 4491.14,1284.81 4491.14,1323.87 4515.7,1348.43
  Top Layer w5.3: 4515.7,1348.43 4589.08,1421.81 4617.08,1421.81 4647.07,1451.8 v1(4647.07,1471.68) ; v1(4587.15,1595.01) 4634.44,1595.01 4673.7,1634.26 4673.7,1648.77 4696.13,1671.2 4705.55,1671.2 4705.75,1671.4 U37.7@4729.47,1671.4
  Bottom Layer w5.3: v1(4587.15,1595.01) 4620.04,1562.12 4620.04,1526.98 4620.12,1526.9 4620.12,1525.99 4647.76,1498.35 4647.76,1472.38 v1(4647.07,1471.68)
AM261_MDIO0_MDC: R223.1 R310.1 U46.2 U48.9 | length 4435.7
  Top Layer w5.3: v1(6079.36,431.43) 6101.59,453.66 6257.28,453.66 6356.66,553.04 6615.34,553.04 v1(6635.94,532.44) ; U46.2@6894.37,1402.53 6944.69,1402.53 v1(6959.69,1387.53) ; U48.9@7199.34,422.21 7230.1,422.21 7253.46,445.57 7257.83,445.57 7263.87,451.62 R223.1@7263.87,451.88 ; R223.1@7265.02,452.27 7295.59,452.27 v1(7295.79,452.47)
  SIG 1 w5.3: v1(6959.69,1387.53) 6960.37,1386.86 6972.39,1386.86 7324.95,1034.3 7324.95,481.63 v1(7295.79,452.47)
  Bottom Layer w5.3: R310.1@4595.43,897.39 4618.8,897.39 4666.37,849.81 4666.37,808.63 4735.55,739.45 4798.72,739.45 4820.97,717.21 4820.97,631.6 4856.93,595.64 4877.82,595.64 4929.48,543.97 5033.45,543.97 5166.84,410.58 5793.79,410.58 5854.25,471.04 6022.96,471.04 6062.57,431.43 v1(6079.36,431.43) ; v1(6635.94,532.44) 6709.38,459 6897.62,459 6911.04,472.42 7014.65,472.42 7050.83,508.61 7152.32,508.61 7208.46,452.47 v1(7295.79,452.47)
AM261_MDIO0_MDIO: U46.4 U48.7 U49.4 | length 1964.8
  Top Layer w5.3: U46.4@6894.37,1441.9 6963.91,1441.9 v1(6983.36,1422.45) ; v1(7155.31,396.62) 7169.09,382.84 U48.7@7199.34,382.84 ; v1(7225.52,738.31) 7226.27,737.56 U49.4@7226.27,703.87
  SIG 1 w5.3: v1(6983.36,1422.45) 7354.16,1051.65 7354.16,458.35 7323.13,427.32 7260.46,427.32 7229.76,396.62 v1(7155.31,396.62) 7183.32,424.63 7204.11,424.63 7295.79,516.31 7295.79,638.79 7226.04,708.54 7226.04,737.79 v1(7225.52,738.31)
AM261_MDIO0_MDIO_L: R224.1 R311.1 U49.3 | length 3178.7
  Top Layer w5.3: v1(6027.5,500.16) 6258.48,500.16 6344.62,586.3 6638.23,586.3 v1(6650.64,598.7) ; U49.3@7226.27,615.29 v1(7264.66,615.29) 7272.64,623.26 7272.64,635.06 R224.1@7275.03,637.46
  Bottom Layer w5.3: R311.1@4593.07,937.13 4611.12,937.13 4678.8,869.46 4678.8,817.14 4744.2,751.74 4807.26,751.74 4981.33,577.67 5030.34,577.67 5172.02,436 5782.42,436 5850.87,504.44 6019.78,504.44 6024.07,500.16 v1(6027.5,500.16) ; v1(6650.64,598.7) 6650.64,556.36 6730.72,476.28 6897.84,476.28 6906.43,484.88 7008.82,484.88 7046.36,522.42 7171.79,522.42 v1(7264.66,615.29)
AM261_MII1_COL: J23.14 U34.E20 | length 2739.7
  Top Layer w5.3: U34.E20@4580.71,1195.24 4623.87,1195.24 4672.56,1243.93 4716.13,1243.93 4778.07,1305.87 v1(4834.61,1305.87) ; v1(6761.47,1847.69) 6778.92,1865.14 J23.14@6778.92,1908.44
  SIG 1 w4.75: v1(4834.61,1305.87) 4855.34,1285.14 4855.34,1258.1 4862.07,1251.37 4931.99,1251.37 4947.88,1267.26 5145.48,1267.26 5166.43,1288.21 5166.43,1413.4 5182.52,1429.49 5276.47,1429.49 5276.68,1429.7 5280.66,1429.7 5307.8,1456.84 5768.92,1456.84 5809.27,1497.19 6425.36,1497.19 6616.59,1688.42 6616.59,1822.7 6619.9,1826 6650.94,1857.04 6752.06,1857.04 6761.41,1847.69 v1(6761.47,1847.69)
AM261_MII2_COL: J21.14 U34.J19 | length 3855.7
  Top Layer w3.94: U34.J19@4555.12,1092.88 4567.91,1105.68 4612.39,1105.68 4612.47,1105.59 4624.25,1105.59
  Top Layer w5.3: 4624.25,1105.59 4656.95,1105.59 4708.98,1157.62 4755.26,1157.62 4776.65,1179.02 4830.7,1179.02 4839.3,1170.42 v1(4840.16,1170.42) ; J21.14@6483.55,91.39 v1@6483.55,123.39
  Top Layer w8: v1@6483.55,123.39 v1(6483.89,123.73)
  SIG 1 w4.75: v1(4840.16,1170.42) 4890.77,1170.42 4918.21,1142.98 4949.57,1142.98 5025.91,1219.32 5200.05,1219.32 5272.74,1292 5548.12,1292 5564.72,1275.4 6087.82,1275.4 6107.12,1294.7 6338.87,1294.7 6733.63,899.94 6733.63,610.92 6685.96,563.25 6397.22,563.25 6222.32,388.36 6222.32,234.39 6274.93,181.78 6303.2,181.78 6425.84,181.78 v1(6483.89,123.73)
AM261_OSPI0_CLK: R88.2 R114.1 R348.1 TP18.1 U26.B2 | length 1016.1
  Top Layer w5.3: TP18.1@3170.86,1187.9 3170.86,1156.88 v1(3171.12,1156.62) 3171.17,1156.66 3241.2,1156.66 U26.B2@3293.89,1103.97 ; v1(3618.98,920.64) 3648.65,950.3 3706.24,950.3 3739.61,916.94 R114.1@3760.84,916.94
  SIG 1 w4.75: v1(3171.12,1156.62) 3170.81,1156.62 3148.01,1133.82 3148.01,1044.44 3201.39,991.06 3457.81,991.06 3488.6,960.27 3579.34,960.27 v1(3618.98,920.64)
  Bottom Layer w5.3: R88.2@3169.16,1129.49 3171.12,1131.45 v1(3171.12,1156.62)
AM261_OSPI0_CSN0: R89.2 R109.1 TP17.1 U26.C2 | length 925.9
  Top Layer w5.3: TP17.1@3166.98,1025.48 v1(3166.98,1053.93) R89.2@3166.98,1081.34 3170.3,1084.66 3273.83,1084.66 U26.C2@3293.89,1064.6 ; v1(3684.3,976.57) 3686.94,979.21 R109.1@3759.39,979.21
  SIG 1 w4.75: v1(3166.98,1053.93) 3166.98,1092.98 3183.06,1109.06 3249.94,1109.06 3261.79,1097.21 3261.79,1029.93 3288.1,1003.63 3464.08,1003.63 3491.14,976.57 v1(3684.3,976.57)
AM261_OSPI0_D0: R100.1 R332.1 R339.2 TP24.1 | length 684.4
  Top Layer w5.3: TP24.1@3418.47,808.32 3418.47,842.1 v1(3416.59,843.98) 3416.9,844.29 R100.1@3440.45,844.29
  SIG 1 w4.75: v1(3416.59,843.98) 3393.57,867 3365.92,867 3357,875.92 3357,895.58 3363.42,902 3585.13,902 3599.47,887.66 3669.71,887.66 3728.6,946.54 3728.6,999.08 3728.41,999.27 3728.41,1005.95 v1(3725.87,1008.49)
  Bottom Layer w5.3: v1(3416.59,843.98) 3440.14,843.98 R339.2@3440.45,844.29 ; v1(3725.87,1008.49) 3737.82,1020.43 R332.1@3760.72,1020.43
AM261_OSPI0_D1: R97.1 R126.1 R342.2 TP22.1 | length 968.3
  Top Layer w5.3: TP22.1@3306.83,808.32 3306.83,843.59 v1(3306.43,843.98) 3306.75,844.29 R97.1@3330.3,844.29 ; v1(3820.08,949.9) 3828.41,941.56 R126.1@3860.48,941.56
  SIG 1 w4.75: v1(3306.43,843.98) 3341.71,808.71 3440.71,808.71 3496.96,864.96 3677.6,864.96 3759.62,946.99 3759.62,1072.91 3771.71,1085 3797.86,1085 3806.96,1075.9 3806.96,963.01 v1(3820.08,949.9)
  Bottom Layer w5.3: v1(3306.43,843.98) 3329.99,843.98 R342.2@3330.3,844.29 ; R342.2@3327,841.92 R342.2@3328.46,843.38
AM261_OSPI0_D2: R103.1 R110.1 R337.1 TP29.1 | length 773.7
  Top Layer w5.3: R103.1@3514.17,1105.45 3562.12,1105.45 v1(3562.21,1105.54) 3562.3,1105.45 TP29.1@3589.89,1105.45 ; v1(3667.15,928.18) 3694.65,928.18 3741.56,881.27 R110.1@3760.72,881.27
  SIG 1 w4.75: v1(3562.21,1105.54) 3525.12,1142.63 3488,1142.63 3469.82,1124.45 3469.82,1016.46 3490.01,996.27 3694.2,996.27 3706.27,984.2 3706.27,958.59 3678.16,930.48 3669.45,930.48 v1(3667.15,928.18)
  Bottom Layer w5.3: R337.1@3527.75,1105.45 3562.12,1105.45 v1(3562.21,1105.54)
AM261_OSPI0_D3: R104.1 R130.1 R336.2 TP28.1 | length 959.3
  Top Layer w5.3: R104.1@3514.17,1017.79 3560.96,1017.79 v1(3562.21,1016.53) 3563.91,1014.83 TP28.1@3563.91,988.08 ; v1(3831.09,1000.05) 3833.22,1000.05 3840.54,1007.37 R130.1@3861.35,1007.37
  SIG 1 w4.75: v1(3562.21,1016.53) 3496.47,1016.53 3486,1027 3486,1114.34 3494.66,1123 3525.85,1123 3541.06,1107.79 3541.06,1077.1 3571.48,1046.68 3612.15,1046.68 3657.27,1091.79 3737.79,1091.79 3765,1119 3819.13,1119 3908,1030.13 3908,1006 3901.9,999.9 v1@3831.23,999.9
  Bottom Layer w5.3: R336.2@3527.75,1017.79 3560.96,1017.79 v1(3562.21,1016.53)
AM261_OSPI0_D4: R105.1 R324.1 R335.2 TP32.1 | length 891.8
  Top Layer w5.3: R105.1@3514.28,1060.68 3592.74,1060.68 3599.14,1067.09 v1(3602.19,1067.09) 3602.4,1067.29 TP32.1@3633.29,1067.29
  SIG 1 w4.75: v1(3602.19,1067.09) 3670.62,1135.51 3894.49,1135.51 3930,1100 3930,1075.9 3969.2,1036.7 3969.2,949.69 3957.51,938 3909.45,938 3881.62,965.83 3881.18,966.27 v1(3881.18,966.82)
  Bottom Layer w5.3: R335.2@3572.39,1063.53 3598.64,1063.53 v1(3602.19,1067.09) ; v1(3881.18,966.82) 3881.18,966.27 3881.62,965.83 3885.68,965.83 3898.96,952.55 R324.1@3898.96,880.3
AM261_OSPI0_D5: R98.1 R122.1 R341.2 TP23.1 | length 930.4
  Top Layer w5.3: TP23.1@3363.67,808.32 3363.67,837.86 3360.98,840.55 v1(3360.98,843.98) 3361.29,844.29 R98.1@3384.85,844.29 ; v1@3831.98,1045.27 3836.77,1050.05 R122.1@3854.97,1050.05
  SIG 1 w4.75: v1(3360.98,843.98) 3383.41,821.56 3432.56,821.56 3487.97,876.97 3674.02,876.97 3749.13,952.08 3749.13,1083.61 3769.96,1104.44 3817.89,1104.44 3870,1052.33 3870,1022 3863.93,1015.93 3849.21,1015.93 v1(3825.92,1039.21)
  Bottom Layer w5.3: v1(3360.98,843.98) 3384.54,843.98 R341.2@3384.85,844.29
AM261_OSPI0_D6: R95.1 R125.1 R345.2 TP21.1 | length 981
  Top Layer w5.3: TP21.1@3250,808.32 3250,843.3 v1(3250.68,843.98) 3251,844.29 R95.1@3274.55,844.29 ; v1(3709.91,869.42) 3709.91,869.19 3719.37,859.73 3816.96,859.73 3820.07,856.62 R125.1@3860.48,856.62
  SIG 1 w4.75: v1(3250.68,843.98) 3226.99,843.98 3204.01,821 3159.07,821 3150.99,812.91 3150.99,786.36 3161.34,776 3222,776 3242.68,796.68 3452.68,796.68 3508,852 3692.49,852 v1(3709.91,869.42)
  Bottom Layer w5.3: v1(3250.68,843.98) 3274.24,843.98 R345.2@3274.55,844.29
AM261_OSPI0_D7: R92.1 R329.1 R347.2 TP20.1 | length 813
  Top Layer w5.3: TP20.1@3196.34,808.32 3196.34,843.52 v1(3195.87,843.98) 3196.19,844.29 R92.1@3219.74,844.29
  SIG 1 w4.75: v1(3195.87,843.98) 3266.89,915 3592.14,915 3606.55,900.59 3667.83,900.59 3718.55,951.31 3718.55,988.52 3707.12,999.94 3707.12,1030.85 v1(3728.52,1052.25)
  Bottom Layer w5.3: v1(3195.87,843.98) 3219.43,843.98 R347.2@3219.74,844.29 ; v1(3728.52,1052.25) 3736.37,1060.1 R329.1@3760.84,1060.1
AM261_OSPI0_DQS: R106.1 R129.1 TP30.1 | length 891.6
  Top Layer w5.3: R106.1@3514.17,1145.11 3551.12,1145.11 v1(3559.59,1153.58) 3561.28,1155.27 TP30.1@3592.79,1155.27 ; v1(3830.7,903.14) 3833.9,899.94 R129.1@3861.01,899.94
  SIG 1 w4.75: v1(3559.59,1153.58) 3562.51,1153.58 3569,1147.09 3919.13,1147.09 3979.25,1086.97 3979.25,916.35 3959.7,896.8 3840.11,896.8 3833.77,903.14 v1(3830.7,903.14)
AM261_OSPI0_DQS_R: R101.2 R106.2 R340.1 U26.C3 | length 250.7
  Top Layer w5.3: U26.C3@3333.26,1064.6 3351.09,1082.43 3415.72,1082.43 3440.66,1107.38 ; 3428.19,1094.91 3440.66,1107.38 ; R340.1@3494.85,1183.71 3494.85,1145.88 R106.2@3494.09,1145.11 3478.39,1145.11 3440.66,1107.38
AM261_OSPI0_ECC_FAIL: R102.1 R330.1 TP26.1 U26.A5 | length 544.3
  Top Layer w5.3: U26.A5@3412,1143.34 3412,1195.61 3468.67,1252.28 3498.46,1252.28 v1(3498.82,1252.61) 3499.02,1252.81 3499.02,1275.02 R102.1@3499.27,1275.27 3499.27,1294.5 TP26.1@3520.49,1315.72
  Bottom Layer w5.3: v1(3498.82,1252.61) 3498.82,1250.94 3519.89,1229.86 3629.85,1229.86 3719.59,1140.12 R330.1@3760.72,1140.12
AM261_OSPI0_RESET_OUT0: R331.1 U25.8 | length 1028.9
  Top Layer w5.3: U25.8@3048.18,1484.11 3048.18,1441.9 v1(3048.35,1441.73) ; v1@3053.83,1435.16 3122.53,1366.47 v1(3122.53,1222.25)
  Bottom Layer w5.3: v1(3122.53,1222.25) 3170.15,1222.25 3309.97,1082.43 3396.21,1082.43 3445.49,1131.71 3576.03,1131.71 3592.21,1147.88 3651.14,1147.88 3706.04,1092.98 R331.1@3759.81,1092.98
AM261_OSPI1_CLK/FSITX0_CLK: R169.1 U54.2 | length 495.8
  Top Layer w5.3: R169.1@4959.55,748.79 4987.35,748.79 4987.41,748.85 5101.45,748.85 5148.7,796.09 5252.72,796.09 5262.64,786.18 5262.64,731.33 5277.95,716.02 5277.95,702.42 5273.76,698.23 5252.53,698.23 v1(5231.95,698.23)
  Bottom Layer w5.3: v1(5231.95,698.23) U54.2@5263.12,698.23
AM261_OSPI1_CSN0/EQEP1_B: R164.1 U54.14 | length 519.9
  Top Layer w5.3: R164.1@4957.22,796.32 4959.74,793.8 5093.66,793.8 5126.28,826.42 5174.57,826.42 5189.36,841.2 5189.36,885.2 5179.47,895.09 5154.17,895.09 5144.5,904.75 5144.5,941.96 5158.02,955.48 5206.2,955.48 v1(5227.22,934.46)
  Bottom Layer w5.3: v1(5227.22,934.46) U54.14@5263.12,934.46
AM261_OSPI1_D0/FSITX0_DATA0: R178.1 U54.3 | length 391.9
  Top Layer w5.3: R178.1@5059.85,816.26 v1(5086.24,816.26)
  Bottom Layer w5.3: v1(5086.24,816.26) 5086.24,783.76 5094,776 5131.92,776 5139.72,768.2 5139.72,759.2 5132.53,752 5091.22,752 5083.2,743.98 5083.2,726.04 5091.32,717.92 U54.3@5263.12,717.92
AM261_OSPI1_D1/FSITX0_DATA1: R168.1 U54.4 | length 383
  Top Layer w5.3: R168.1@4957.22,662.42 4981.58,662.42 5029.58,614.42 5113.24,614.42 5224.07,725.25 5224.07,735.8 v1(5225.88,737.61)
  Bottom Layer w5.3: v1(5225.88,737.61) U54.4@5263.12,737.61
AM261_OSPI1_D2/FSIRX0_CLK: R182.1 U54.5 | length 314.3
  Top Layer w5.3: R182.1@5060.16,684.02 5060.16,663.64 5089.65,634.14 5117.18,634.14 5173.11,690.08 v1(5173.11,737.44)
  Bottom Layer w5.3: v1(5173.11,737.44) 5192.96,757.29 U54.5@5263.12,757.29
AM261_OSPI1_D3/FSIRX0_DATA0/EQEP0_A: R162.1 U54.6 | length 480.9
  Top Layer w5.3: R162.1@4955.05,705.05 4955.72,705.73 5076.22,705.73 5083.45,698.5 5083.45,667.63 5092.85,658.23 5124.23,658.23 5149.04,683.04 5149.04,739.96 5165.39,756.3 5244.75,756.3 5247.86,759.4 5247.86,773.61 5244.5,776.98 v1(5225.88,776.98)
  Bottom Layer w5.3: v1(5225.88,776.98) U54.6@5263.12,776.98
AM261_OSPI1_D4/FSIRX0_DATA1/EQEP0_B: R176.1 U54.7 | length 334.5
  Top Layer w5.3: R176.1@5057.33,726.94 5079.29,726.94 5097,709.23 5097,684.99 5106.99,675 5122,675 5137,690 5137,762.69 5151.34,777.03 v1(5173.11,777.03)
  Bottom Layer w5.3: v1(5173.11,777.03) 5193.75,777.03 5213.38,796.66 U54.7@5263.12,796.66
AM261_OSPI1_D5/EQEP0_INDEX: R165.1 U54.11 | length 524.9
  Top Layer w5.3: R165.1@4957.22,839.92 4984.43,839.92 4984.52,839.83 5114.22,839.83 5128.7,854.31 v1(5168.32,854.31)
  Bottom Layer w5.3: v1(5168.32,854.31) 5168.18,854.31 5155.7,841.84 5121.64,841.84 5109.91,830.1 5109.91,806.19 5116.5,799.6 5188.21,799.6 5200.63,812.03 5200.63,860.03 5216,875.4 U54.11@5263.12,875.4
AM261_OSPI1_D6/EQEP0_STROBE: R179.1 U54.12 | length 402.2
  Top Layer w5.3: R179.1@5059.85,878.37 5087.07,878.37 v1(5087.15,878.28)
  Bottom Layer w5.3: v1(5087.15,878.28) 5108.62,878.28 5115.87,885.54 5115.87,966.93 5115.79,967.01 5115.79,987.42 5124.07,995.7 5137.39,995.7 5145.4,987.69 5145.4,904.36 5154.68,895.09 U54.12@5263.12,895.09
AM261_OSPI1_D7/EQEP1_A: R177.1 U54.13 | length 385.4
  Top Layer w5.3: R177.1@5059.69,770 5092.95,770 5134.95,812 5177.82,812 5202.75,836.92 5202.75,896.19 v1(5166.43,932.5)
  Bottom Layer w5.3: v1(5166.43,932.5) 5198.87,932.5 5216.61,914.77 U54.13@5263.12,914.77
AM261_OSPI1_DQS/EQEP1_STROBE: U34.U19 U54.15 | length 833.9
  Top Layer w3.94: U34.U19@4555.12,888.16 4567.91,900.95 4624.25,900.95
  Top Layer w5.3: 4624.25,900.95 4813.47,900.95 4853.65,860.77 4992.03,860.77 4995.64,857.16 5096.86,857.16 5125,885.29 5125,958.39 5144.3,977.69 v1(5166.89,977.69)
  Bottom Layer w5.3: v1(5166.89,977.69) 5190.44,954.14 U54.15@5263.12,954.14
AM261_OSPI1_ECC_FAIL/EQEP1_INDEX: R166.1 U54.16 | length 396.6
  Top Layer w5.3: R166.1@4957.22,898.29 4959.22,900.29 5092.88,900.29 5107.81,915.22 5107.81,982.46 5123.35,998 5207.68,998 v1(5226.57,979.11)
  Bottom Layer w5.3: v1(5226.57,979.11) 5231.85,973.83 U54.16@5263.12,973.83
AM261_OSPI1_RESET_OUT0: R108.1 U25.9 | length 1061.3
  Top Layer w5.3: U25.9@3067.87,1484.11 3067.87,1465.72 3081.27,1452.32 3081.71,1452.76 3190.08,1452.76 3205.64,1468.32 3240.32,1468.32 3251.3,1457.34 3251.3,1392.02 3266.33,1376.99 3291.08,1376.99 3305.29,1391.2 3333.24,1391.2 3356.87,1367.56 3398.92,1367.56 3426.63,1395.27 3496.81,1395.27 3598.95,1293.13 3598.95,1194.47 3655.76,1137.66 3655.76,1095.99 3724.26,1027.49 3750.66,1027.49 R108.1@3757.85,1020.3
